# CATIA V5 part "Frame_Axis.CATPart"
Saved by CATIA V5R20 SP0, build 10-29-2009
Part number: Frame_Axis
Material "Steel": density 7860 kg/m3, Young's modulus 2e+11 Pa, Poisson ratio 0.266, thermal expansion 1.17e-05 1/K
Bounding box of the stored display mesh (mm): x -150 to 150, y -10 to 10, z -9.985 to 13
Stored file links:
  C:\Users\syed\Desktop\GITHUB\Advance-Smart-GPS-Electromagnetic-Brake-System\NIHAAL\Hardware\CATIA\Model_01\Part\Frame_Axis.CATPart
  D:\DREAD STUDIO SOFTWARE\Catia_V5\Catia_V5_Installed\intel_a\startup\materials\Catalog.CATMaterial
  D:\DREAD STUDIO SOFTWARE\Catia_V5\Catia_V5_Installed\intel_a\resources\graphic\figures\CATIA_EnvironmentMap_Square1_512x512.jpg
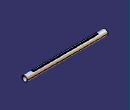
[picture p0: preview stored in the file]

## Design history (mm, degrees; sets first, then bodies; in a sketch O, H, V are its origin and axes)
Body1 (main body), material "Steel"
  Sketch1 on yz-plane, origin (0, 0, 0), H (0, 1, 0), V (0, 0, 1)
    circle A1 centre (0, 0) radius 10
    radius A1 = 10
  Pad1: profile Sketch1, direction (1, 0, 0), length 150, mirrored extent
  Sketch2 on end face of Pad1, origin (150, 0, 0), H (0, 1, 0), V (0, 0, 1)
    circle A1 centre (0, 0) radius 9
    radius A1 = 9
  Pocket1: profile Sketch2, direction (-1, 0, 0), through (limit type 3)
  Sketch3 on yz-plane, origin (0, 0, 0), H (0, 1, 0), V (0, 0, 1)
    point P1 (-3, 13)
    line L1 (-3, 13) -> (3, 13)
    line L2 (3, 13) -> (3, 9.5394)
    line L3 (-3, 9.5394) -> (-3, 13)
    point P3 (3, 8)
    point P4 (-3, 8)
    axis line L4 (0, 8) -> (0, 10.6796)
    point P5 (0, 8)
    projected circle E1 centre (0, 0) radius 10 from edge [face of Pad1 from Sketch1.A1 | end face of Pad1]
    projected arc E2 centre (0, 0) radius 10 from (3, 9.5394) to (-3, 9.5394) ccw from edge [face of Pad1 from Sketch1.A1 | end face of Pad1]
    point P7 (3, 9.5394)
    point P8 (-3, 9.5394)
    distance P3 P4 = 6
    distance P4 P1 = 5
    horizontal: L1 H
    vertical: L2 V, L3 V, L4 V
    coincidence: P5 V, E1 P7, E1 P8
  Pad2: profile Sketch3, direction (1, 0, 0), length 120, mirrored extent
  Fillet1: radius 1, on edge [face of Pad2 from Sketch3.L1 | face of Pad2 from Sketch3.L2]; edge [face of Pad2 from Sketch3.L3 | face of Pad2 from Sketch3.L1]; edge [face of Pad2 from Sketch3.L1 | end face of Pad2]; edge [start face of Pad2 | face of Pad2 from Sketch3.L1]; edge [start face of Pad2 | face of Pad1 from Sketch1.A1]; edge [face of Pad2 from Sketch3.L2 | face of Pad1 from Sketch1.A1]; edge [face of Pad1 from Sketch1.A1 | face of Pad2 from Sketch3.L3]; face of Pad2 from Sketch3.L3; start face of Pad2; edge [face of Pad1 from Sketch1.A1 | end face of Pad2]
